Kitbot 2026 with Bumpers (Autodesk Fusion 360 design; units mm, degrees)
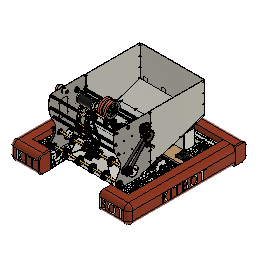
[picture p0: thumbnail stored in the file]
description: STEP AP242
part number: Kitbot 2026
description: 1/2" Hex x 1-1/8" OD (Flanged)
part number: 1/2" Hex x 1-1/8" OD (Flanged)
description: Core
part number: Core
description: Flap
part number: Flap
description: id21
part number: id21
description: Hex lock nut with nylon insert #10-32
part number: Hex lock nut with nylon insert #10-32
description: KB-26007: Brace Shaft
part number: KB-26007: Brace Shaft
description: Socket button head cap screw #10-32 x 0.5
part number: Socket button head cap screw #10-32 x 0.5
description: KB-26019: Hood Plate Spacer
part number: KB-26019: Hood Plate Spacer
description: Part 29
part number: Part 29
base_feature "Base Feature1"
base_feature "Base Feature1"
base_feature "Base Feature1"
base_feature "Base Feature1"
base_feature "Base Feature1"
base_feature "Base Feature1"
base_feature "Base Feature1"
base_feature "Base Feature1"
base_feature "Base Feature1"
base_feature "Base Feature1"
base_feature "Base Feature1"
base_feature "Base Feature1"
base_feature "Base Feature1"
base_feature "Base Feature1"
base_feature "Base Feature1"
base_feature "Base Feature1"
base_feature "Base Feature1"
base_feature "Base Feature1"
base_feature "Base Feature1"
base_feature "Base Feature1"
base_feature "Base Feature1"
base_feature "Base Feature1"
base_feature "Base Feature1"
base_feature "Base Feature1"
base_feature "Base Feature1"
base_feature "Base Feature1"
base_feature "Base Feature1"
base_feature "Base Feature1"
base_feature "Base Feature1"
base_feature "Base Feature1"
base_feature "Base Feature1"
base_feature "Base Feature1"
base_feature "Base Feature1"
base_feature "Base Feature1"
base_feature "Base Feature1"
base_feature "Base Feature1"
base_feature "Base Feature1"
base_feature "Base Feature1"
base_feature "Base Feature1"
base_feature "Base Feature1"
base_feature "Base Feature1"
base_feature "Base Feature1"
base_feature "Base Feature1"
base_feature "Base Feature1"
base_feature "Base Feature1"
base_feature "Base Feature1"
base_feature "Base Feature1"
base_feature "Base Feature1"
base_feature "Base Feature1"
base_feature "Base Feature1"
base_feature "Base Feature1"
base_feature "Base Feature1"
base_feature "Base Feature1"
base_feature "Base Feature1"
base_feature "Base Feature1"
base_feature "Base Feature1"
base_feature "Base Feature1"
base_feature "Base Feature1"
base_feature "Base Feature1"
base_feature "Base Feature1"
base_feature "Base Feature1"
base_feature "Base Feature1"
base_feature "Base Feature1"
base_feature "Base Feature1"
base_feature "Base Feature1"
base_feature "Base Feature1"
base_feature "Base Feature1"
base_feature "Base Feature1"
base_feature "Base Feature1"
base_feature "Base Feature1"
base_feature "Base Feature1"
base_feature "Base Feature1"
base_feature "Base Feature1"
base_feature "Base Feature1"
base_feature "Base Feature1"
base_feature "Base Feature1"
base_feature "Base Feature1"
base_feature "Base Feature1"
base_feature "Base Feature1"
base_feature "Base Feature1"
base_feature "Base Feature1"
base_feature "Base Feature1"
base_feature "Base Feature1"
base_feature "Base Feature1"
base_feature "Base Feature1"
base_feature "Base Feature1"
base_feature "Base Feature1"
base_feature "Base Feature1"
base_feature "Base Feature1"
base_feature "Base Feature1"
base_feature "Base Feature1"
base_feature "Base Feature1"
base_feature "Base Feature1"
base_feature "Base Feature1"
base_feature "Base Feature1"
base_feature "Base Feature1"
base_feature "Base Feature1"
base_feature "Base Feature1"
base_feature "Base Feature1"
base_feature "Base Feature1"
base_feature "Base Feature1"
base_feature "Base Feature1"
base_feature "Base Feature1"
base_feature "Base Feature1"
base_feature "Base Feature1"
base_feature "Base Feature1"
base_feature "Base Feature1"
base_feature "Base Feature1"
base_feature "Base Feature1"
base_feature "Base Feature1"
base_feature "Base Feature1"
as_built_joint "As-built1"
joint "Assemble1" alignAngle 0 alignOffsetX 0 alignOffsetY 36 alignOffsetZ 0
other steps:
create_component "CreateComponent1"
create_component "CreateComponent2"
create_component "CreateComponent3"
create_component "CreateComponent4"
create_component "CreateComponent5"
create_component "CreateComponent6"
create_component "CreateComponent7"
create_component "CreateComponent8"
create_component "CreateComponent9"
create_component "CreateComponent10"
create_component "CreateComponent11"
create_component "CreateComponent12"
create_component "CreateComponent13"
create_component "CreateComponent14"
create_component "CreateComponent15"
create_component "CreateComponent16"
create_component "CreateComponent17"
create_component "CreateComponent18"
create_component "CreateComponent19"
create_component "CreateComponent20"
create_component "CreateComponent21"
create_component "CreateComponent22"
create_component "CreateComponent23"
create_component "CreateComponent24"
create_component "CreateComponent25"
create_component "CreateComponent26"
create_component "CreateComponent27"
create_component "CreateComponent28"
create_component "CreateComponent29"
create_component "CreateComponent30"
create_component "CreateComponent31"
create_component "CreateComponent32"
create_component "CreateComponent33"
create_component "CreateComponent34"
create_component "CreateComponent35"
create_component "CreateComponent36"
create_component "CreateComponent37"
create_component "CreateComponent38"
create_component "CreateComponent39"
create_component "CreateComponent1"
create_component "CreateComponent40"
create_component "CreateComponent1"
create_component "CreateComponent2"
create_component "CreateComponent3"
create_component "CreateComponent41"
create_component "CreateComponent42"
create_component "CreateComponent43"
create_component "CreateComponent44"
create_component "CreateComponent45"
create_component "CreateComponent46"
create_component "CreateComponent47"
create_component "CreateComponent48"
create_component "CreateComponent49"
create_component "CreateComponent50"
create_component "CreateComponent51"
create_component "CreateComponent52"
create_component "CreateComponent53"
create_component "CreateComponent54"
create_component "CreateComponent55"
create_component "CreateComponent56"
create_component "CreateComponent57"
create_component "CreateComponent58"
create_component "CreateComponent59"
create_component "CreateComponent60"
create_component "CreateComponent1"
create_component "CreateComponent61"
create_component "CreateComponent62"
create_component "CreateComponent63"
create_component "CreateComponent64"
create_component "CreateComponent65"
create_component "CreateComponent66"
create_component "CreateComponent67"
create_component "CreateComponent68"
create_component "CreateComponent69"
create_component "CreateComponent70"
create_component "CreateComponent1"
create_component "CreateComponent2"
create_component "CreateComponent3"
create_component "CreateComponent4"
create_component "CreateComponent5"
create_component "CreateComponent6"
create_component "CreateComponent1"
create_component "CreateComponent2"
create_component "CreateComponent1"
create_component "CreateComponent2"
create_component "CreateComponent3"
create_component "CreateComponent4"
create_component "CreateComponent5"
create_component "CreateComponent7"
create_component "CreateComponent1"
create_component "CreateComponent2"
create_component "CreateComponent3"
create_component "CreateComponent4"
create_component "CreateComponent8"
create_component "CreateComponent1"
create_component "CreateComponent9"
create_component "CreateComponent1"
create_component "CreateComponent10"
create_component "CreateComponent1"
create_component "CreateComponent11"
create_component "CreateComponent1"
create_component "CreateComponent2"
create_component "CreateComponent1"
create_component "CreateComponent1"
create_component "CreateComponent2"
create_component "CreateComponent3"
create_component "CreateComponent4"
create_component "CreateComponent1"
create_component "CreateComponent1"
create_component "CreateComponent2"
create_component "CreateComponent2"
create_component "CreateComponent3"
create_component "CreateComponent1"
create_component "CreateComponent2"
create_component "CreateComponent3"
create_component "CreateComponent4"
create_component "CreateComponent5"
create_component "CreateComponent6"
create_component "CreateComponent7"
create_component "CreateComponent8"
create_component "CreateComponent9"
create_component "CreateComponent10"
create_component "CreateComponent11"
create_component "CreateComponent12"
create_component "CreateComponent13"
create_component "CreateComponent14"
create_component "CreateComponent15"
create_component "CreateComponent16"
create_component "CreateComponent17"
create_component "CreateComponent18"
create_component "CreateComponent19"
create_component "CreateComponent20"
create_component "CreateComponent21"
create_component "CreateComponent3"
create_component "CreateComponent1"
create_component "CreateComponent1"
create_component "CreateComponent1"
create_component "CreateComponent2"
create_component "CreateComponent4"
create_component "CreateComponent1"
create_component "CreateComponent2"
create_component "CreateComponent3"
create_component "CreateComponent4"
create_component "CreateComponent5"
create_component "CreateComponent1"
create_component "CreateComponent2"
create_component "CreateComponent3"
create_component "CreateComponent6"
create_component "CreateComponent7"
create_component "CreateComponent8"
create_component "CreateComponent9"
create_component "CreateComponent10"
create_component "CreateComponent11"
create_component "CreateComponent12"
create_component "CreateComponent13"
create_component "CreateComponent14"
create_component "CreateComponent15"
create_component "CreateComponent16"
create_component "CreateComponent17"
create_component "CreateComponent18"
create_component "CreateComponent19"
create_component "CreateComponent20"
create_component "CreateComponent21"
create_component "CreateComponent22"
create_component "CreateComponent23"
create_component "CreateComponent24"
create_component "CreateComponent25"
create_component "CreateComponent26"
create_component "CreateComponent27"
create_component "CreateComponent28"
create_component "CreateComponent29"
create_component "CreateComponent30"
create_component "CreateComponent12"
create_component "CreateComponent1"
joint_origin "JointOrigin2"
joint_origin "JointOrigin2"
